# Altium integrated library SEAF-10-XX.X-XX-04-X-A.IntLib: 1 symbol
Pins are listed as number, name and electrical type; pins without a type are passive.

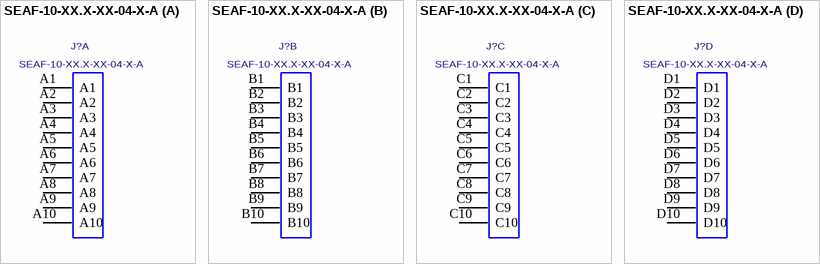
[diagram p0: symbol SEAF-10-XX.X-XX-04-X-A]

## SEAF-10-XX.X-XX-04-X-A
designator J?
Socket Array Assembly, Surface Mount, 0.050" Pitch, 40 pins.; MANUFACTURER: SAMTEC
footprint SEAF-10-XX.X-XX-04-X-A
part A pins: A1, A2, A3, A4, A5, A6, A7, A8, A9, A10
part B pins: B1, B2, B3, B4, B5, B6, B7, B8, B9, B10
part C pins: C1, C2, C3, C4, C5, C6, C7, C8, C9, C10
part D pins: D1, D2, D3, D4, D5, D6, D7, D8, D9, D10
